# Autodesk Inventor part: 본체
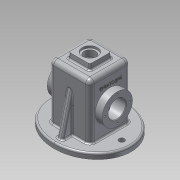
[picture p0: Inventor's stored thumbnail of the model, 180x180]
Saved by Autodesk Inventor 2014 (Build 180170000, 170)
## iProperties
Created: 2017-07
Part Number: 본체
Material: Aluminum 6061
Document SubType Name: Modeling
Designer: user
Density: 2.71 g/cm^3
Appearance: Aluminum - Flat
Author: user
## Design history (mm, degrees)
sketch "Sketch1"
  geometry: L1 (0, 0)-(37, 0); L2 (0, 0)-(-37, 0); L3 (-37, 0)-(-37, 100); L4 (-37, 100)-(37, 100); L5 (37, 100)-(37, 0)
  constraints: 10 end point
  dimensions: "d2" = 74 distance between parallel lines of L3 L5; "d3" = 100 distance between parallel lines of L2 L4; "d4" = 37 distance from line of L3 L1.start
extrude "Extrusion1" new body sketch "Sketch1" stored distance "d5" = 74; taper "d6" = 0 deg
workplane "Work Plane1"
sketch "Sketch2"
  geometry: L1 (37, -57)-(57, -57); L2 (57, -57)-(57, -17); L3 (57, -17)-(17, -17); L4 (17, -17)-(17, -57); L5 (17, -57)-(37, -57); 1 further point
  constraints: 10 end point
  dimensions: "d8" = 20 distance from line of L5 point (37, -37); "d9" = 20 distance from line of L4 point (37, -37); "d10" = 40 distance of L1.end L2.end
extrude "Extrusion2" join sketch "Sketch2" stored distance "d11" = 74; taper "d12" = 0 deg
feature "FaceDraft1" dims angle "d13" = 5 deg
sketch "Sketch3"
  geometry: C1 r 14 at (37, -37); 1 further point
  constraints: 1 centre point, 1 coincident
  dimensions: "d14" = 28 diameter of C1
extrude "Extrusion3" cut sketch "Sketch3" distance "d15" = 4; taper "d16" = 0 deg
sketch "Sketch5"
  geometry: L1 (37, 0)-(-37, 0) reference; L2 (-37, 0)-(-37, 100) reference; L3 (-37, 100)-(-20, 100) reference; L4 (-20, 100)-(-19.125, 110) reference; L5 (-19.125, 110)-(-14, 110) reference; L6 (-14, 110)-(-14, 106) reference; L7 (-14, 106)-(14, 106) reference; L8 (14, 106)-(14, 110) reference; L9 (14, 110)-(19.125, 110) reference; L10 (19.125, 110)-(20, 100) reference; L11 (20, 100)-(37, 100) reference; L12 (37, 100)-(37, 0) reference; L13 (50, 45)-(50, 72.5); L14 (50, 72.5)-(-50, 72.5); L15 (-50, 72.5)-(-50, 17.5); L16 (-50, 17.5)-(50, 17.5); L17 (50, 17.5)-(50, 45); L18 (-50, 45)-(50, 45); 1 further point
  constraints: 12 end point, 1 midpoint
  dimensions: "d21" = 45 distance from line of L1 L18.start; "d22" = 55 distance between parallel lines of L14 L16; "d23" = 100 distance between parallel lines of L17 L15
revolve "Revolution1" sketch "Sketch5" stored, may be unused: angle "d24" = 90 deg
workplane "Work Plane2"
sketch "Sketch7"
  geometry: L1 (0, 0)-(-58, 0); L2 (0, 0)-(58, 0); L3 (58, 0)-(-58, 0); L4 (0, 0)-(0, -65); L5 (0, -65)-(-75, -65); L6 (-75, -65)-(-75, 0); L7 (-75, 0)-(-58, 0); L8 (75, 0)-(75, 65); L9 (0, 65)-(75, 65); L10 (0, 65)-(-75, 65); L11 (-75, 0)-(-75, 65); L12 (75, 0)-(75, -65); L13 (75, -65)-(0, -65); L14 (0, 0)-(0, 65); L15 (58, 0)-(75, 0); 1 other entity
  constraints: 32 end point, 1 coincident, 1 midpoint, 6 other
  dimensions: "d29" = 75 distance between parallel lines of L4 L12; "d30" = 75 distance between parallel lines of L6 L4; "d31" = 65 distance between parallel lines of L13 L2; "d32" = 65 distance between parallel lines of L9 L2; "d33" = 116 distance of L1.end L2.end
extrude "Extrusion5" join sketch "Sketch7" distance "d34" = 10; taper "d35" = 0 deg
sketch "Sketch9"
  geometry: L1 (19.125, 110)-(20, 100) reference; L2 (20, 100)-(37, 100) reference; L3 (37, 100)-(37, 72.5) reference; L4 (37, 72.5)-(50, 72.5) reference; L5 (50, 72.5)-(50, 17.5) reference; L6 (50, 17.5)-(37, 17.5) reference; L7 (37, 17.5)-(37, 0) reference; L8 (37, 0)-(75, 0) reference; L9 (75, 0)-(75, -10) reference; L10 (75, -10)-(-75, -10) reference; L11 (-75, -10)-(-75, 0) reference; L12 (-75, 0)-(-37, 0) reference; L13 (-37, 0)-(-37, 17.5) reference; L14 (-37, 17.5)-(-50, 17.5) reference; L15 (-50, 17.5)-(-50, 72.5) reference; L16 (-50, 72.5)-(-37, 72.5) reference; L17 (-37, 72.5)-(-37, 100) reference; L18 (-37, 100)-(-20, 100) reference; L19 (-20, 100)-(-19.125, 110) reference; L20 (-19.125, 110)-(-14, 110) reference; L21 (-14, 110)-(-14, 106) reference; L22 (-14, 106)-(14, 106) reference; L23 (14, 106)-(14, 110) reference; L24 (14, 110)-(19.125, 110) reference; L25 (0, -10)-(-32, -10); L26 (-32, -10)-(-32, 27.5); L27 (-32, 27.5)-(-25, 34.5); L28 (-25, 34.5)-(-25, 77.5); L29 (-30, 82.5)-(-25, 77.5); L30 (-30, 82.5)-(-30, 92); L31 (-37, 100)-(37, 100) reference; L32 (-27, 95)-(0, 95); L33 (0, 95)-(0, -10); L34 (29.624, -10)-(32, -10); L35 (30, 82.5)-(25, 77.5); L36 (30, 82.5)-(30, 92); L37 (37, 72.5)-(37, 100); L38 (50, 72.5)-(37, 72.5); L39 (37, 100)-(20, 100); L40 (27, 95)-(0, 95); L41 (25, 34.5)-(25, 77.5); L42 (32, 27.5)-(25, 34.5); L43 (37, 100)-(-37, 100); L44 (32, -10)-(32, 27.5); L45 (0, -10)-(32, -10); L46 (-75, -10)-(75, -10); L47 (37, 17.5)-(50, 17.5); L48 (75, 0)-(37, 0); L49 (37, 0)-(37, 17.5); L50 (14, 106)-(-14, 106); L51 (20, 100)-(19.125, 110); L52 (19.125, 110)-(14, 110); L53 (14, 110)-(14, 106); A1 r 3 centre (-27, 92) between (-27, 95) and (-30, 92); A2 r 3 centre (27, 92) between (30, 92) and (27, 95); 1 further point
  constraints: 56 end point, 13 symmetric about line, 4 point on circle, 4 point on line, 2 centre point, 2 tangent, 1 midpoint, 1 parallel, 1 other
  dimensions: "d52" = 135 deg angle of L26 L27; "d53" = 135 deg angle of L29 L30; "d54" = 5 distance between parallel lines of L32 L18; "d55" = 3 radius of A1; "d56" = 55 vertical distance of L26.end L29.start
extrude "Extrusion6" cut sketch "Sketch9" stored distance "d57" = 64; taper "d58" = 0 deg
sketch "Sketch10"
  geometry: C1 r 27.5 at (0, 0) reference; C2 r 16 at (0, 0); 1 further point
  constraints: 1 centre point, 1 coincident
  dimensions: "d59" = 32 diameter of C2
extrude "Extrusion7" cut sketch "Sketch10" stored distance "d60" = 64; taper "d61" = 0 deg
sketch "Sketch11"
  geometry: C1 r 14 at (0, 0) reference; C2 r 10.5 at (0, 0)
  constraints: 1 centre point, 1 coincident
  dimensions: "d62" = 21 diameter of C2
extrude "Extrusion8" cut sketch "Sketch11" distance "d63" = 20; taper "d64" = 0 deg
feature "FaceDraft2" dims angle "d65" = 5 deg
sketch "Sketch12"
  geometry: L1 (22.5, 0)-(-22.5, 0); L2 (0, -22.5)-(0, 22.5); C1 r 27.5 at (0, 0) reference; A1 r 22.5 centre (0, 0) between (22.5, 0) and (-22.5, 0); 5 further points
  constraints: 5 coincident, 4 end point, 4 point on circle, 1 centre point
  dimensions: "d66" = 45 diameter of A1
hole "Hole1" sketch "Sketch12" at (22.5, 0), (0, -22.5), (0, 22.5), (-22.5, 0) diameter "d67" = 3.459; stored, may be unused: countersink angle "d71" = 90 deg, drill point angle "d73" = 118 deg; dims "d68" = 8, "d69" = 4, "d70" = 2, "d72" = 10
sketch "Sketch13"
  geometry: L1 (-22.5, 0)-(22.5, 0); L2 (0, -22.5)-(0, 22.5); C1 r 27.5 at (0, 0) reference; A1 r 22.5 centre (0, 0) between (-22.5, 0) and (22.5, 0); 5 further points
  constraints: 5 coincident, 4 end point, 4 point on circle, 1 centre point
  dimensions: "d74" = 45 diameter of A1
hole "Hole2" sketch "Sketch13" at (-22.5, 0), (0, -22.5), (22.5, 0), (0, 22.5) diameter "d75" = 3.459; stored, may be unused: countersink angle "d79" = 90 deg, drill point angle "d81" = 118 deg; dims "d76" = 8, "d77" = 4, "d78" = 2, "d80" = 10
sketch "Sketch14"
  geometry: L1 (0, 0)-(-58, 0); L2 (0, 0)-(58, 0); 2 further points; 1 other entity
  constraints: 4 end point, 2 coincident, 1 other
  dimensions: "d82" = 116 distance of L1.end L2.end; "d83" = 58 distance of L1.start L2.end
hole "Hole3" sketch "Sketch14" at (58, 0), (-58, 0) diameter "d84" = 10; stored, may be unused: countersink angle "d88" = 90 deg, drill point angle "d90" = 0 deg; dims "d85" = 8, "d86" = 4, "d87" = 2, "d89" = 10
workplane "Work Plane4"
workplane "Work Plane5"
sketch "Sketch18"
  geometry: L1 (-88.345, -32.671)-(-88.345, 33.604); L2 (-88.345, 33.604)-(21.335, 33.604); L3 (21.335, 33.604)-(21.335, -32.671); L4 (21.335, -32.671)-(-88.345, -32.671); 1 further point
  constraints: 2 other
emboss "Emboss2" sketch "Sketch18" dims "d98" = 0.5, "d99" = 0
sketch "Sketch19"
  geometry: L1 (-20, 100)-(-19.125, 110) reference; L2 (-19.125, 110)-(-14, 110) reference; L3 (-14, 110)-(-14, 106) reference; L4 (-14, 106)-(-10.5, 106) reference; L5 (-10.5, 106)-(-10.5, 95) reference; L6 (-10.5, 95)-(-32, 95) reference; L7 (-32, 95)-(-32, -10) reference; L8 (-32, -10)-(-65, -10) reference; L9 (-65, -10)-(-65, 0) reference; L10 (-65, 0)-(-37, 0) reference; L11 (-37, 0)-(-37, 100) reference; L12 (-37, 100)-(-20, 100) reference; L13 (19.125, 110)-(20, 100) reference; L14 (20, 100)-(37, 100) reference; L15 (37, 100)-(37, 0) reference; L16 (37, 0)-(65, 0) reference; L17 (65, 0)-(65, -10) reference; L18 (65, -10)-(32, -10) reference; L19 (32, -10)-(32, 95) reference; L20 (32, 95)-(10.5, 95) reference; L21 (10.5, 95)-(10.5, 106) reference; L22 (10.5, 106)-(14, 106) reference; L23 (14, 106)-(14, 110) reference; L24 (14, 110)-(19.125, 110) reference; L25 (65, -10)-(32, -10); L26 (65, 0)-(55, 0); L27 (55, 0)-(37, 72.194); L28 (37, 72.194)-(37, 0); L29 (55, 0)-(37, 0); L30 (0, 0)-(0, -10); L31 (-55, 0)-(-37, 0); L32 (-37, 0)-(-65, 0); L33 (-65, 0)-(-55, 0); L34 (-65, 0)-(-65, -10); L35 (-65, -10)-(-32, -10); L36 (-65, -10)-(-32, -10); L37 (-55, 0)-(-37, 72.194); L38 (-37, 72.194)-(-37, 0)
  constraints: 28 end point, 3 point on line, 2 symmetric about line
  dimensions: "d107" = 14 deg angle of L27 L17; "d108" = 10 distance from line of L17 L26.end
extrude "Extrusion9" join sketch "Sketch19" stored distance "d109" = 10; taper "d110" = 0 deg
fillet "Fillet1" dims "d111" = 8
fillet "Fillet2" dims "d112" = 8
fillet "Fillet6" dims "d116" = 3
fillet "Fillet7" dims "d117" = 3
fillet "Fillet8" dims "d118" = 3
fillet "Fillet9" dims "d119" = 3
fillet "Fillet10" dims "d120" = 3
fillet "Fillet11" dims "d121" = 3
fillet "Fillet12" dims "d122" = 3
fillet "Fillet13" dims "d123" = 3
chamfer "Chamfer1" distance "d124" = 1; stored, may be unused: second distance "d125" = 2, angle "d126" = 45 deg
body "Solid1"
node "Project Cut Edges1"
node "Project Cut Edges5"
node "Project Cut Edges6"
other parameters: "d36" = 135 deg, "d37" = 7, "d39" = 135 deg, "d97" = 61
